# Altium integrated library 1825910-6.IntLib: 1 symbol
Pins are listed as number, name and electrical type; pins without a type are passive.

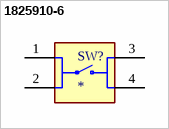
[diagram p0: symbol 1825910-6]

## 1825910-6
designator SW?
Switch Tactile OFF (ON) SPST Round Button PC Pins 0.05A 24VDC 100000Cycles 1.57N Thru-Hole Loose; MP: 1825910-6
footprint SW_1825910-6-4
pins: 1, 2, 3, 4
